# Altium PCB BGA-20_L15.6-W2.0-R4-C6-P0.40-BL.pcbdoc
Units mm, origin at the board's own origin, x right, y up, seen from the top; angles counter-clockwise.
Board outline 15.07 x 14.42 mm, 2 copper layers (Top Layer, Bottom Layer), stack 0 mm thick; 1 components, 0 nets, 20 pads, 0 vias.
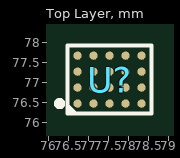
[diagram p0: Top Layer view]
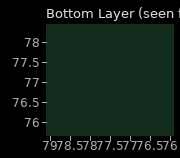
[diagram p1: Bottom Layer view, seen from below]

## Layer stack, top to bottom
Top Layer: signal copper (thickness not stored)
Bottom Layer: signal copper (thickness not stored)

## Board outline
84.919,69.85 69.85,69.85 69.85,84.265 84.919,84.265

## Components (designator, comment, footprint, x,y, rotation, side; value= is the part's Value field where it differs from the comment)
U? "" BGA-20_L15.6-W2.0-R4-C6-P0.40-BL 77.52,77.065 r0 top

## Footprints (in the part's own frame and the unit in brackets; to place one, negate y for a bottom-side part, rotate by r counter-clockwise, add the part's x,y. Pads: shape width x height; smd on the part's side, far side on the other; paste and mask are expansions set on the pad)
BGA-20_L15.6-W2.0-R4-C6-P0.40-BL [mil]
  round 8.19 smd: A1(-31.5,-23.62) A2(-31.5,-7.87) A3(-31.5,7.87) A4(-31.5,23.62) B1(-15.75,-23.62) B2(-15.75,-7.87) B3(-15.75,7.87) B4(-15.75,23.62) C1(0,-23.62) C2(0,-7.87) C3(0,7.87) C4(0,23.62) D1(15.75,-23.62) D2(15.75,-7.87) D3(15.75,7.87) D4(15.75,23.62) E1(31.5,-23.62) E2(31.5,-7.87) E3(31.5,7.87) E4(31.5,23.62)
  silkscreen extent -52,-34 41,33

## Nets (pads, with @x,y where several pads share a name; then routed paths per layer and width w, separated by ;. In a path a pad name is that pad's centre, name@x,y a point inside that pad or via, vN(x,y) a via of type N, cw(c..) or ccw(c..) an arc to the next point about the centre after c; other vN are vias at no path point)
pads on no net: U?.A1 U?.A2 U?.A3 U?.A4 U?.B1 U?.B2 U?.B3 U?.B4 U?.C1 U?.C2 U?.C3 U?.C4 U?.D1 U?.D2 U?.D3 U?.D4 U?.E1 U?.E2 U?.E3 U?.E4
